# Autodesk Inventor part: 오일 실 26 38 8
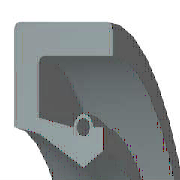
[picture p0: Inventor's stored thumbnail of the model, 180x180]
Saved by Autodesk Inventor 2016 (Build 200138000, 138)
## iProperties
IsCustomPart: 1
Created: 2012-02
Part Number: 오일 실 26 38 8
Material: 고무
Description: 오일-실
Document SubType Name: Modeling
Standard: KS B 2804
Designer: mduedu
Standards Organization: KS
Language: ko-KR
Size Designation: S - 26 38 8
Categories: <MemberInstance><Categories><Category DisplayName="샤프트 부품" InternalName="7f7aeb1f-a693-4053-b835-cee3144e0d98" Mnemonic="SHFT"><Category DisplayName="실링" Intern
Density: 0.93 g/cm^3
Appearance: 고무 - 검은색 - 버전 1.1
Author: mduedu
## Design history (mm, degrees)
revolve "본체" stored, may be unused: angle "d17" = 90 deg
revolve "스프링1" stored, may be unused: angle "d18" = 90 deg
body "Solid1"
sketch "스케치1"
  geometry: L1 (0, 19)-(8, 19); L2 (8, 19)-(8, 17.75); L3 (8, 17.75)-(1.75, 17.75); L4 (0, 19)-(0, 15.1); L5 (0, 15.1)-(1.75, 14.75); L6 (1.75, 14.75)-(4.9, 13); L7 (4.9, 13)-(0, 13); L8 (6.3, 13.875)-(6.3, 15.1); L9 (0, 0)-(9.586, 0) reference; L10 (4.9, 13)-(6.3, 13.875); L11 (0, 18)-(0, -3) reference; L12 (-1.917, 0)-(11.503, 0) reference; L13 (4.2, 15.1)-(1.75, 15.59); L14 (1.75, 15.59)-(1.75, 17.75); L15 (6.3, 15.1)-(5.6, 15.1); C1 r 0.455 at (4.9, 15.1); A1 r 0.7 centre (4.9, 15.1) between (5.6, 15.1) and (4.2, 15.1)
  constraints: 26 end point, 5 horizontal alignment, 4 perpendicular, 2 centre point, 2 collinear, 2 horizontal, 2 parallel, 2 point on circle, 2 point on line, 2 vertical alignment, 1 coincident
  dimensions: "d0" = 38 diameter of L1 L9 (= SD2); "d1" = 27.75 diameter of L8.start L9 (= ABDM); "d2" = 1.25 distance of L1.end L2.end (computed from SD); "d3" = 0.91 diameter of C1 (= SPDI); "d4" = 1.4 diameter of A1 (= SPDA); "d5" = 26 diameter of L6.end L9 (= NND); "d6" = 29.5 diameter of L5.end L9 (= TKDM); "d7" = 30.2 diameter of L4.end L9 (= HLDM); "d8" = 4.9 distance from line of C1.centre L4 (= SPDST); "d9" = 6.3 distance between parallel lines of L8 L4 (= SDI); "d10" = 8 distance between parallel lines of L2 L4 (= SWDT); "d12" = 1.75 distance between parallel lines of L14 L4 (= SD)
fillet "모깎기1" dims "d11" = 0.3 (= RR)
other parameters: "SD2" = 38 [user parameter; used in 1 equation term], "SWDT" = 8 [user parameter; used in 1 equation term], "RR" = 0.3 [user parameter; used in 1 equation term], "SD" = 1.75 [user parameter; used in 2 equation terms], "NND" = 26 [user parameter; used in 1 equation term], "SPDA" = 1.4 [user parameter; used in 1 equation term], "SPDI" = 0.91 [user parameter; used in 1 equation term], "TKDM" = 29.5 [user parameter; used in 1 equation term], "HLDM" = 30.2 [user parameter; used in 1 equation term], "ABDM" = 27.75 [user parameter; used in 1 equation term], "SDI" = 6.3 [user parameter; used in 1 equation term], "SPDST" = 4.9 [user parameter; used in 1 equation term], "d13" = 0, "d14" = 0, "d15" = 0, "LAB" = 0.35 [user parameter]
